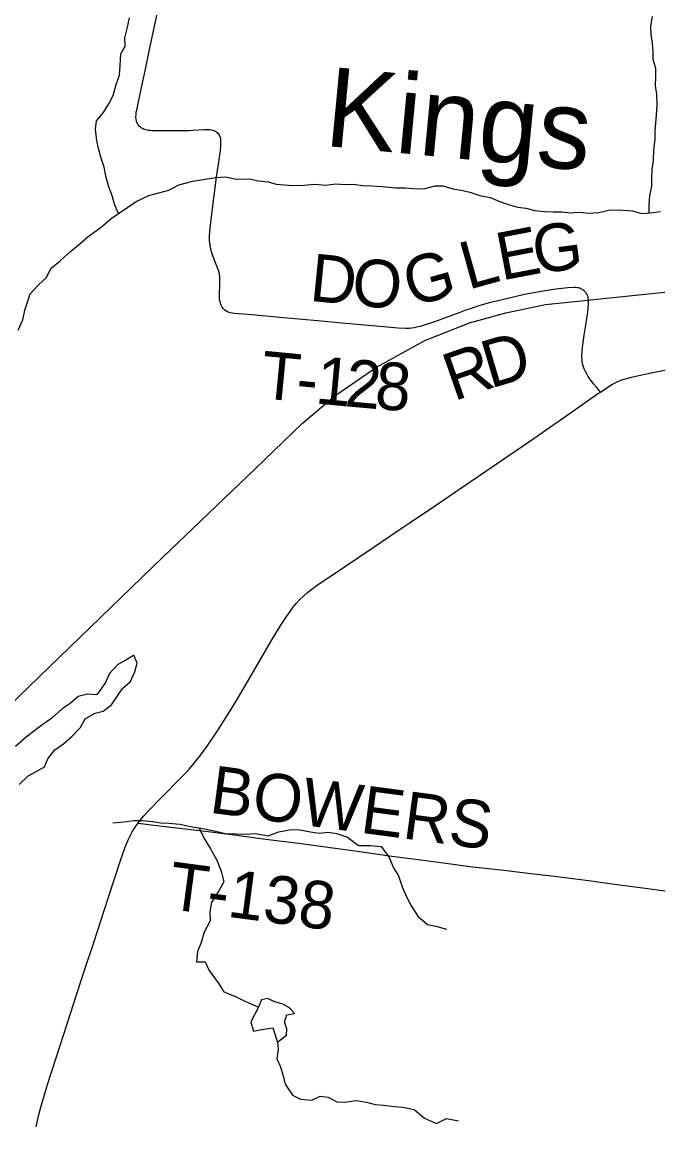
# Model space of a CAD drawing. Extents: x 0 to 1101, y 0 to 440.
# Drawn here: x 845.256 to 846.014, y 371.091 to 372.41 of the extents above; entities that cross this region are included whole.
import ezdxf

# ---------------------------------------------------------------- set-up
doc = ezdxf.new("R2010")
doc.units = 0
for name, color, linetype in [('GM_X_Minor_Lake', 7, 'Continuous'), ('GM_X_Minor_River', 7, 'Continuous'), ('GM_X_Minor_River_Text', 7, 'Continuous'), ('GM_X_Rail_Line', 7, 'Continuous'), ('GM_X_State_Route', 7, 'Continuous'), ('GM_X_Township_Road', 7, 'Continuous'), ('GM_X_Township_Road_Text', 7, 'Continuous')]:
    doc.layers.add(name, color=color, linetype=linetype)

msp = doc.modelspace()

# ---------------------------------------------------------------- linework, layer by layer
at = {"layer": 'GM_X_Minor_Lake'}
for points in [[(845.3885, 371.6543), (845.3792, 371.6485), (845.3696, 371.6432), (845.3597, 371.6327), (845.355, 371.6221), (845.3446, 371.6073), (845.3335, 371.6078), (845.3225, 371.6052), (845.3129, 371.5969), (845.3033, 371.5905), (845.291, 371.5792), (845.2776, 371.5698), (845.2607, 371.557), (845.2477, 371.5454)], [(845.2522, 371.5), (845.2626, 371.5106), (845.2722, 371.5158), (845.2821, 371.5211), (845.2864, 371.5309), (845.2945, 371.5415), (845.3048, 371.5487), (845.3148, 371.5573), (845.3248, 371.5679), (845.3306, 371.5785), (845.3425, 371.5852), (845.352, 371.5878), (845.362, 371.5953), (845.3685, 371.6048), (845.3751, 371.6146), (845.3847, 371.6233), (845.3901, 371.6347), (845.3929, 371.6449), (845.3888, 371.6545), (845.3885, 371.6543)], [(845.5601, 371.1928), (845.5708, 371.201), (845.5713, 371.2086), (845.5684, 371.217), (845.5712, 371.2253), (845.5803, 371.2267), (845.5743, 371.2336), (845.5664, 371.2379), (845.5569, 371.2406), (845.5483, 371.2446), (845.541, 371.2431), (845.5375, 371.2345)], [(845.5375, 371.2345), (845.5281, 371.2167), (845.5314, 371.2057), (845.5413, 371.2078), (845.5546, 371.2099), (845.5601, 371.1928)]]:
    msp.add_lwpolyline(points, dxfattribs=at)
at = {"layer": 'GM_X_Minor_River'}
for points in [[(845.3704, 372.1818), (845.3663, 372.1917), (845.363, 372.2028), (845.3589, 372.2135), (845.3559, 372.2245), (845.3534, 372.2371), (845.3497, 372.2478), (845.3471, 372.2577), (845.3445, 372.2683), (845.3431, 372.2824), (845.3444, 372.2923), (845.3524, 372.3021), (845.359, 372.3127), (845.3641, 372.3225), (845.3676, 372.3358), (845.3715, 372.3467), (845.3724, 372.3585), (845.3733, 372.3722), (845.3783, 372.3816), (845.378, 372.3915), (845.3812, 372.404), (845.3836, 372.4154)], [(846.0035, 372.1825), (846.0032, 372.1922), (846.0041, 372.2028), (846.0065, 372.2142), (846.0066, 372.2241), (846.007, 372.2343), (846.0083, 372.2453), (846.0088, 372.2575), (846.0104, 372.2704), (846.0105, 372.2803), (846.0113, 372.2897), (846.0122, 372.2996), (846.0127, 372.3118), (846.0124, 372.3239), (846.011, 372.3346), (846.0111, 372.3448), (846.0112, 372.3547), (846.0082, 372.3657), (846.0079, 372.3752), (846.0073, 372.3851), (846.0058, 372.3954), (846.0052, 372.4053), (846.0072, 372.417)], [(845.3013, 372.1258), (845.3136, 372.1367), (845.3247, 372.1461), (845.3343, 372.1544), (845.35, 372.1653), (845.3616, 372.1758), (845.3914, 372.1961), (845.4067, 372.2032), (845.4304, 372.2094), (845.4426, 372.2158), (845.4591, 372.2202), (845.469, 372.222), (845.4861, 372.2245), (845.4979, 372.2255), (845.5109, 372.2228), (845.5265, 372.223), (845.5375, 372.2206), (845.5489, 372.2194), (845.5584, 372.2166), (845.5679, 372.2158), (845.5782, 372.2153), (845.5915, 372.2156), (845.6045, 372.2166), (845.6178, 372.2157), (845.6296, 372.2171), (845.641, 372.2163), (845.6509, 372.2166), (845.6615, 372.2153), (845.6722, 372.2149), (845.6851, 372.214), (845.7007, 372.2123), (845.7129, 372.2122), (845.7258, 372.211), (845.7361, 372.2116), (845.748, 372.2149), (845.7575, 372.2149), (845.7692, 372.2113), (845.7791, 372.2094), (845.7894, 372.207), (845.8012, 372.2031), (845.8137, 372.2007), (845.8262, 372.1956), (845.8357, 372.1925), (845.8467, 372.1894), (845.8562, 372.1881), (845.8669, 372.1854), (845.8783, 372.1841), (845.8889, 372.1837), (845.8992, 372.1836), (845.9091, 372.1827), (845.9198, 372.1834), (845.9312, 372.1822), (845.9434, 372.1828), (845.9548, 372.1857), (845.9662, 372.186), (845.9833, 372.1851), (845.9944, 372.1816), (846.0046, 372.1826), (846.0168, 372.1841)], [(845.2507, 372.0426), (845.2565, 372.0547), (845.2589, 372.0665), (845.262, 372.076), (845.2652, 372.0858), (845.2752, 372.0964), (845.2848, 372.1054), (845.2898, 372.116), (845.3013, 372.1258)], [(845.3637, 371.4546), (845.377, 371.4556), (845.3892, 371.4573), (845.3987, 371.4572), (845.4116, 371.4559), (845.4211, 371.4546), (845.4306, 371.4541), (845.4438, 371.4528), (845.4582, 371.4495), (845.4711, 371.4475), (845.4847, 371.445), (845.498, 371.4418), (845.5112, 371.4412), (845.5219, 371.4407), (845.5333, 371.4417), (845.5488, 371.4388), (845.5618, 371.4436), (845.5762, 371.4465), (845.5868, 371.4459), (845.5993, 371.4435), (845.6096, 371.4422), (845.6206, 371.4432), (845.6308, 371.4416), (845.6437, 371.4372), (845.6568, 371.4272), (845.6709, 371.4274), (845.6838, 371.426), (845.6934, 371.413), (845.6986, 371.4008), (845.7045, 371.3912), (845.7089, 371.3779), (845.714, 371.3661), (845.7192, 371.3561), (845.7274, 371.3431), (845.739, 371.3331), (845.7488, 371.3311), (845.7617, 371.3275)], [(845.4668, 371.4482), (845.4728, 371.4357), (845.4802, 371.4234), (845.4876, 371.4097), (845.4931, 371.3967), (845.496, 371.3838), (845.4901, 371.3732), (845.4812, 371.3597), (845.4795, 371.3483), (845.4797, 371.3373), (845.4727, 371.3241), (845.4687, 371.3105), (845.4648, 371.3007), (845.4635, 371.2886), (845.4737, 371.2884), (845.4785, 371.2781), (845.4893, 371.2636), (845.496, 371.2525), (845.5092, 371.2477), (845.5194, 371.2423), (845.5296, 371.238), (845.5375, 371.2345), (845.5281, 371.2167), (845.5314, 371.2057), (845.5413, 371.2078), (845.5546, 371.2099), (845.5601, 371.1928), (845.5607, 371.1844), (845.5594, 371.1727), (845.5638, 371.1631), (845.5667, 371.1525), (845.5692, 371.1426), (845.5778, 371.1295), (845.5876, 371.1245), (845.6012, 371.1235), (845.6108, 371.128), (845.6206, 371.1271), (845.6308, 371.1212), (845.6403, 371.1211), (845.6536, 371.1228), (845.6661, 371.1208), (845.6767, 371.118), (845.6865, 371.1174), (845.6998, 371.1157), (845.7097, 371.1149), (845.7229, 371.1124), (845.7353, 371.102), (845.7496, 371.0957), (845.7615, 371.1013), (845.7759, 371.0988)]]:
    msp.add_lwpolyline(points, dxfattribs=at)
at = {"layer": 'GM_X_Rail_Line'}
msp.add_lwpolyline([(844.1346, 370.5459), (844.3997, 370.7937), (844.8041, 371.1833), (845.1901, 371.5461), (845.4225, 371.7708), (845.5333, 371.8771), (845.5894, 371.9309), (845.6284, 371.9639), (845.6782, 371.9983), (845.7357, 372.0303), (845.789, 372.0514), (845.8324, 372.0633), (845.8796, 372.0733), (846.2786, 372.1146), (846.3759, 372.1225), (846.4631, 372.1257), (846.5327, 372.1208), (846.59, 372.1143), (846.7044, 372.0937), (846.8234, 372.0596), (847.2573, 371.9407)], dxfattribs=at)
at = {"layer": 'GM_X_State_Route'}
msp.add_lwpolyline([(845.2722, 371.0914), (845.2752, 371.1048), (845.2779, 371.115), (845.2821, 371.1298), (845.2858, 371.1419), (845.2905, 371.1567), (845.3008, 371.1886), (845.3132, 371.227), (845.3296, 371.2773), (845.3405, 371.3103), (845.3582, 371.3645), (845.3729, 371.4096), (845.379, 371.4266), (845.3828, 371.4358), (845.385, 371.4406), (845.3867, 371.4436), (845.389, 371.4473), (845.3911, 371.4505), (845.394, 371.4542), (845.3961, 371.457), (845.4007, 371.4626), (845.4056, 371.4678), (845.4098, 371.4722), (845.4167, 371.4795), (845.4506, 371.5141), (845.4543, 371.5181), (845.4593, 371.5237), (845.4636, 371.5291), (845.4675, 371.5338), (845.4719, 371.5398), (845.4763, 371.5459), (845.4893, 371.5655), (845.5076, 371.5943), (845.5187, 371.613), (845.5529, 371.6722), (845.564, 371.6902), (845.5679, 371.6963), (845.5712, 371.7012), (845.5752, 371.7068), (845.5785, 371.7113), (845.5824, 371.7162), (845.5866, 371.7208), (845.5909, 371.725), (845.5958, 371.7294), (845.6011, 371.7335), (845.6062, 371.7374), (845.6398, 371.7599), (845.6743, 371.7831), (845.7052, 371.804), (845.7171, 371.8119), (845.7474, 371.8325), (845.79, 371.8616), (845.8249, 371.8854), (845.8633, 371.9117), (845.9225, 371.9529), (845.9419, 371.9663), (845.9452, 371.9686), (845.9532, 371.9741), (845.9565, 371.9762), (845.9596, 371.978), (845.9629, 371.9798), (845.9658, 371.9811), (845.9696, 371.9827), (845.9734, 371.984), (845.978, 371.9853), (845.9824, 371.9865), (845.9946, 371.9892), (846.0098, 371.9923), (846.0512, 372.0006)], dxfattribs=at)
at = {"layer": 'GM_X_Township_Road'}
for points in [[(845.9452, 371.9686), (845.9405, 371.9744), (845.9371, 371.9786), (845.9327, 371.9843), (845.9307, 371.9872), (845.9284, 371.9912), (845.927, 371.9938), (845.9259, 371.9962), (845.925, 371.9986), (845.9244, 372.0009), (845.9238, 372.003), (845.9235, 372.0051), (845.9233, 372.0076), (845.9232, 372.0101), (845.9236, 372.0175), (845.9243, 372.0249), (845.9258, 372.0366), (845.9278, 372.0483), (845.9301, 372.0642), (845.931, 372.0735), (845.9311, 372.0765), (845.931, 372.0785), (845.9307, 372.0806), (845.9304, 372.0821), (845.9298, 372.0838), (845.929, 372.0856), (845.9283, 372.0867), (845.9276, 372.0876), (845.9266, 372.0888), (845.9254, 372.0898), (845.9244, 372.0906), (845.9234, 372.0912), (845.922, 372.092), (845.9205, 372.0925), (845.9191, 372.0928), (845.9175, 372.0931), (845.9157, 372.0932), (845.9138, 372.0933), (845.9063, 372.093), (845.8921, 372.0915), (845.8768, 372.0891), (845.8548, 372.0849), (845.83, 372.0792), (845.8125, 372.075), (845.8, 372.0714), (845.7935, 372.0693), (845.7835, 372.0658), (845.7777, 372.0637), (845.7485, 372.053), (845.7338, 372.048), (845.7301, 372.0469), (845.726, 372.0459), (845.7232, 372.0454), (845.7199, 372.0448), (845.7169, 372.0446), (845.7131, 372.0443), (845.7038, 372.0447), (845.6735, 372.0475), (845.6413, 372.0505), (845.6079, 372.0535), (845.59, 372.0552), (845.5584, 372.0579), (845.5343, 372.0602), (845.5139, 372.062), (845.5091, 372.0624), (845.5059, 372.0628), (845.5038, 372.0632), (845.5023, 372.0636), (845.5012, 372.064), (845.5, 372.0646), (845.4987, 372.0653), (845.4974, 372.0662), (845.4963, 372.0672), (845.4952, 372.0684), (845.4942, 372.0699), (845.4932, 372.0716), (845.4925, 372.0733), (845.492, 372.0751), (845.4915, 372.0772), (845.491, 372.0806), (845.4908, 372.0849), (845.4913, 372.0966), (845.4913, 372.1017), (845.4912, 372.1067), (845.491, 372.1087), (845.4905, 372.1113), (845.4897, 372.1142), (845.4887, 372.117), (845.4847, 372.1267), (845.4814, 372.136), (845.4798, 372.1432), (845.4791, 372.15), (845.4791, 372.1556), (845.4796, 372.1643), (845.4816, 372.181), (845.4834, 372.1939), (845.4858, 372.2123), (845.4875, 372.2253), (845.4897, 372.2406), (845.492, 372.2566), (845.4925, 372.2619), (845.4927, 372.2647), (845.4927, 372.2667), (845.4926, 372.269), (845.4924, 372.2707), (845.4921, 372.2721), (845.4917, 372.2737), (845.4911, 372.275), (845.4904, 372.276), (845.4895, 372.277), (845.4885, 372.2779), (845.4872, 372.2789), (845.4861, 372.2796), (845.4844, 372.2803), (845.4831, 372.2807), (845.4815, 372.2811), (845.4793, 372.2814), (845.4772, 372.2815), (845.4722, 372.2814), (845.4591, 372.2807), (845.4549, 372.2804), (845.4496, 372.2802), (845.4267, 372.2802), (845.4106, 372.2805), (845.4083, 372.2806), (845.4063, 372.2809), (845.4034, 372.2815), (845.402, 372.2818), (845.4003, 372.2824), (845.399, 372.283), (845.3978, 372.2837), (845.3966, 372.2847), (845.3955, 372.2857), (845.3945, 372.287), (845.3936, 372.2881), (845.3926, 372.29), (845.392, 372.2917), (845.3914, 372.2944), (845.3912, 372.2968), (845.3914, 372.2999), (845.3917, 372.3026), (845.3922, 372.3049), (845.394, 372.3132), (845.398, 372.3321), (845.4021, 372.3522), (845.4078, 372.3796), (845.4143, 372.4089), (845.42, 372.4373)], [(845.394, 371.4542), (845.4004, 371.4532), (845.4093, 371.4519), (845.4398, 371.4485), (845.4775, 371.4439), (845.5114, 371.4397), (845.5372, 371.4363), (845.5557, 371.4339), (845.5914, 371.4293), (845.6203, 371.4254), (845.6554, 371.4206), (845.6966, 371.4147), (845.731, 371.4102), (845.7667, 371.4055), (845.7894, 371.4024), (845.8301, 371.3978), (845.8523, 371.3953), (845.8967, 371.3898), (845.9342, 371.3851), (845.9478, 371.3832), (845.965, 371.3807), (845.9958, 371.3767), (846.0481, 371.3696)]]:
    msp.add_lwpolyline(points, dxfattribs=at)

# ---------------------------------------------------------------- texts
at = {"layer": 'GM_X_Minor_River_Text'}
msp.add_text('Kings', height=0.09468, rotation=354.5562, dxfattribs=at).set_placement((845.6146, 372.2626))
at = {"layer": 'GM_X_Township_Road_Text'}
for s, height, rotation, p in [('E', 0.0568, 10.8821, (845.8272, 372.1016)), ('G', 0.0568, 7.4779, (845.868, 372.1095)), ('L', 0.0568, 15.5186, (845.7874, 372.0905)), ('D', 0.0568, 354.33, (845.5972, 372.0776)), ('G', 0.0568, 15.8753, (845.7198, 372.0699)), ('O', 0.0568, 354.4489, (845.6471, 372.0727)), ('D', 0.0568, 16.5028, (845.8138, 371.9726)), ('T', 0.0568, 354.506, (845.5384, 371.9614)), ('R', 0.0568, 19.2718, (845.7704, 371.9574)), ('1', 0.0568, 354.6033, (845.6041, 371.9551)), ('2', 0.0568, 354.8882, (845.6392, 371.9518)), ('8', 0.0568, 355.8654, (845.6751, 371.9486)), ('-', 0.0568, 354.5321, (845.5808, 371.9573)), ('BOWERS', 0.05682, 352.4275, (845.4777, 371.4667)), ('T-138', 0.05682, 352.463, (845.4279, 371.3519))]:
    msp.add_text(s, height=height, rotation=rotation, dxfattribs=at).set_placement(p)

doc.saveas('drawing.dxf')
